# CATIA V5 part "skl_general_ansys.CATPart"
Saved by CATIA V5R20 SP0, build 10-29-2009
Part number: skl_general
Publications: "point A", "point B", "point C", "point D", "point E", "point F", "point G", "point H"
Bounding box of the stored display mesh (mm): x 0 to 0, y 0 to 208, z -1 to 117
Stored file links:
  C:\Users\Cédric\Documents\IFMA-2A\IAO\Projet IAO\ccascaro\skl_general_ansys.CATPart
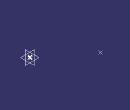
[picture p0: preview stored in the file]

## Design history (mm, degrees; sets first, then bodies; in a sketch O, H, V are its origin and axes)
Set1
  Point1 "point A": type OnPlane, Support yz-plane, H 0, V 0, Direction (0, 1, 0)
  Point2 "point B": type OnPlane, Support yz-plane, H 2.07, V 2.17, Direction (0, 1, 0)
  Point3 "point C": type OnPlane, Support yz-plane, H 0.96, V 2.63, Direction (0, 1, 0)
  Point4 "point D": type OnPlane, Support yz-plane, H 2.4, V 0, Direction (0, 1, 0)
  Point5 "point E": type OnPlane, Support yz-plane, H 1.52, V 2.4, Direction (0, 1, 0)
  Point6 "point F": type OnPlane, Support yz-plane, H 1.52, V 1.4, Direction (0, 1, 0)
  Point7 "point G": type OnPlane, Support yz-plane, H 208, V 117, Direction (0, 1, 0)
  Point8 "point H": type OnPlane, Support yz-plane, H 0, V -1, Direction (0, 1, 0)
Body1 (main body)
